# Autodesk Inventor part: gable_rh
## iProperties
Created: 2005-05
Part Number: gable_rh
Material: cherry
Document SubType Name: Modeling
Designer: a.campbell
Manufacturer: Standard
Standards Organization: Custom
LENGTH_1: 464.000 mm
WIDTH_1: 423.000 mm
THICKNESS_1: 19.000 mm
LENGTH: 464.000 mm
WIDTH: 423.000 mm
THICKNESS: 19.000 mm
Author: a.campbell
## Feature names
1. Derived Body1 [Tagging]
